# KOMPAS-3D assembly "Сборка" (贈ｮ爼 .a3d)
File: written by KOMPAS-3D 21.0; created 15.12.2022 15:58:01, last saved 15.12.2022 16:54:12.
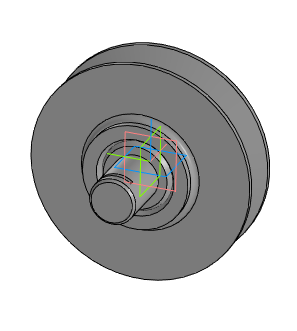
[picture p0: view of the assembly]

Document properties: Полное имя файла: C:\git\VlSU\IGS(AutoCAD)\rk3\Сборка.a3d; Автор: gggchaseggg@gmail.com

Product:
- Part/product: Сборка
    Масса: 12.207336
    Форматы листов документа: A4
    source file: Сборка-спецификация.spw
  - Component [detail]: Ось  | pos. 2  | Масса: 2.283245; source file: Bolt.m3d
  - Component [detail]: Втулка  | pos. 3  | Масса: 1.321575; source file: Vtulka.m3d
  - Component [detail]: Ролик  | pos. 1  | Масса: 8.602516; source file: Rolik.m3d

Referenced files in C:\git\VlSU\IGS(AutoCAD)\rk3\: Rolik.m3d, Vtulka.m3d, Bolt.m3d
